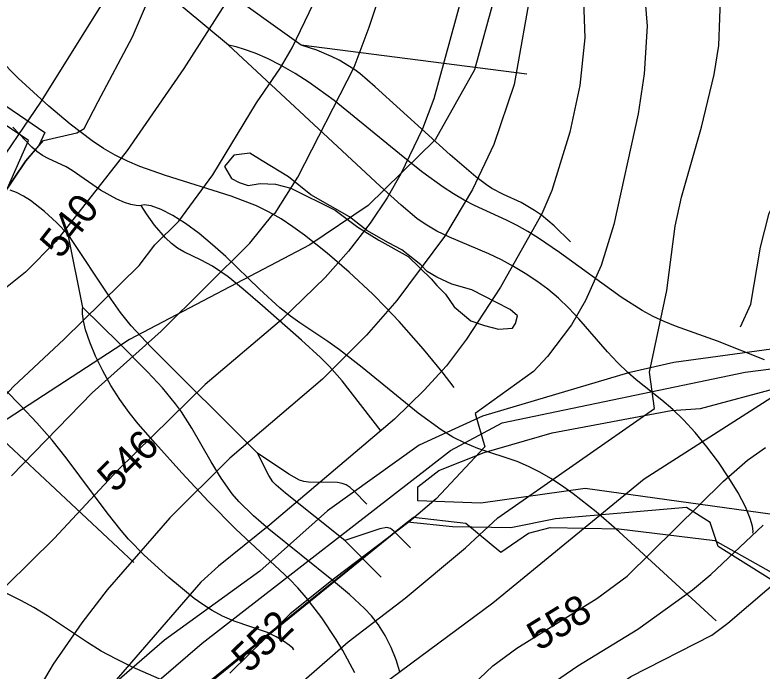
# Model space of a CAD drawing. Extents: x -709584 to -702006, y -1161789 to -1157496.
# Drawn here: x -708540.3 to -708283.8, y -1158766.7 to -1158541.7 of the extents above; entities that cross this region are included whole.
import ezdxf

# ---------------------------------------------------------------- set-up
doc = ezdxf.new("R2010")
doc.units = 0
for name, color, linetype in [('102_obvod PÚ', 7, 'Continuous'), ('110_silnice II. třídy a III. třídy', 7, 'Continuous'), ('120_vrstevnice hlavní', 7, 'Continuous'), ('121_vrstevnice hlavní_popis', 7, 'Continuous'), ('122_vrstevnice základní', 7, 'Continuous'), ('124_vrstevnice doplňková', 7, 'Continuous'), ('408_BPEJ_linie', 7, 'Continuous'), ('411_akumulovaný odtok', 7, 'Continuous'), ('419_LPIS PB', 7, 'Continuous')]:
    doc.layers.add(name, color=color, linetype=linetype)

msp = doc.modelspace()

# ---------------------------------------------------------------- linework, layer by layer
at = {"layer": '102_obvod PÚ'}
for points in [[(-708547.68, -1158611.72), (-708535.59, -1158584.74), (-708593.47, -1158546.09)], [(-707921.75, -1158971.03), (-707999.13, -1158885.41), (-708014.04, -1158899.97), (-708117.65, -1158840.95), (-708144.91, -1158823.83), (-708143.18, -1158817.96), (-708120.65, -1158790.72), (-708182.31, -1158754.97), (-708195.79, -1158778.16), (-708236.74, -1158752.81), (-708244.62, -1158757.84), (-708255.93, -1158750.88), (-708298.89, -1158724.01), (-708301.57, -1158715.74), (-708309.76, -1158710.63), (-708354.66, -1158714.54), (-708370.07, -1158717.61), (-708390.11, -1158717.27), (-708405.56, -1158715.63), (-708506.26, -1158796.6), (-708529.03, -1158816.51), (-708541.87, -1158842.13), (-708566.99, -1158883.81), (-708618.46, -1158935.49)]]:
    msp.add_lwpolyline(points, dxfattribs=at)
at = {"layer": '110_silnice II. třídy a III. třídy'}
msp.add_lwpolyline([(-708704.41, -1159007.15), (-708617.29, -1158919.6), (-708571.81, -1158874.15), (-708546.81, -1158830.34), (-708531.01, -1158804.51), (-708475.96, -1158757.15), (-708390.75, -1158691.13), (-708373.04, -1158681.56), (-708289.6, -1158664.21), (-708263.74, -1158660.86), (-708218.75, -1158674.74), (-708130.19, -1158710.62), (-708061.25, -1158767.55), (-707984.07, -1158831.3), (-707891.2, -1158926.02), (-707845.98, -1158974.16)], dxfattribs=at)
at = {"layer": '120_vrstevnice hlavní'}
for points in [[(-708409.92, -1158419.84), (-708416.34, -1158434.7), (-708434.49, -1158471.56), (-708444.2, -1158490.13), (-708455.2, -1158514.13), (-708468.35, -1158538.14), (-708482.35, -1158559.99), (-708501.78, -1158588.14), (-708526.21, -1158619.43), (-708536.64, -1158629.85), (-708559.07, -1158647.71)], [(-708345.48, -1158524.14), (-708344.63, -1158549.56), (-708346.34, -1158565.85), (-708349.77, -1158581.85), (-708355.91, -1158601.85), (-708359.34, -1158609.85), (-708373.63, -1158635), (-708385.2, -1158652.86), (-708392.06, -1158662), (-708399.77, -1158670.43), (-708409.92, -1158680.28), (-708452.78, -1158716.57), (-708470.35, -1158730.72), (-708476.49, -1158736.29), (-708506.21, -1158770.57), (-708513.62, -1158779.44), (-708518.35, -1158786.4), (-708533.12, -1158807.02), (-708523.37, -1158816.78), (-708575.5, -1158908.3)], [(-708494.35, -1158934.3), (-708464.92, -1158897.29), (-708460.06, -1158889.01), (-708440.2, -1158848.15), (-708435.92, -1158840.72), (-708430.77, -1158833.29), (-708424.77, -1158826.29), (-708414.49, -1158817.15), (-708400.34, -1158809.01), (-708394.34, -1158804.15), (-708378.06, -1158788.86), (-708366.06, -1158779.57), (-708356.91, -1158771.72), (-708347.06, -1158765), (-708326.48, -1158752.43), (-708307.62, -1158738.86), (-708301.34, -1158733.57), (-708283.34, -1158716.72)]]:
    msp.add_lwpolyline(points, dxfattribs=at)
at = {"layer": '122_vrstevnice základní'}
for points in [[(-708359.2, -1158388.56), (-708364.01, -1158398.84), (-708367.5, -1158412.36), (-708369.25, -1158425.89), (-708374.63, -1158482.13), (-708376.34, -1158492.13), (-708387.06, -1158536.14), (-708396.49, -1158570.42), (-708400.34, -1158580.71), (-708407.77, -1158596.14), (-708412.49, -1158604.42), (-708418.34, -1158613.14), (-708425.77, -1158622.71), (-708433.77, -1158631.71), (-708448.78, -1158646.28), (-708474.92, -1158668.43), (-708504.92, -1158697.86), (-708526.78, -1158721.29), (-708543.21, -1158737.43)], [(-708422.34, -1158397.27), (-708431.34, -1158415.56), (-708438.35, -1158426.99), (-708472.2, -1158475.99), (-708487.06, -1158501.56), (-708497.49, -1158517.13), (-708531.49, -1158571.57), (-708549.35, -1158597.71), (-708575.78, -1158629.28), (-708597.5, -1158656.28), (-708622.78, -1158686.14), (-708642.07, -1158713.86), (-708659.5, -1158736.57), (-708677.79, -1158762.15), (-708685.64, -1158775.86), (-708700.36, -1158805.58), (-708711.65, -1158830.72), (-708716.22, -1158842.15), (-708721.93, -1158860.44), (-708724.79, -1158871.87), (-708732.22, -1158910.73), (-708735.5, -1158924.44), (-708739.07, -1158933.58)], [(-708360.32, -1158513.61), (-708362.77, -1158531.28), (-708368.91, -1158565.56), (-708375.91, -1158586.14), (-708383.2, -1158601.57), (-708392.77, -1158617.71), (-708409.2, -1158639.57), (-708419.63, -1158651.57), (-708434.63, -1158666.57), (-708466.49, -1158693.71), (-708487.06, -1158714.14), (-708508.64, -1158738.86), (-708517.35, -1158750.15), (-708527.21, -1158764.43), (-708541.07, -1158788.01), (-708554.07, -1158812.72), (-708557.35, -1158820.72), (-708568.49, -1158843.47), (-708576.84, -1158861.02), (-708581.85, -1158872.45), (-708572.39, -1158881.09)], [(-708541.49, -1158699.72), (-708513.78, -1158671.28), (-708490.06, -1158650.14), (-708459.63, -1158620), (-708451.63, -1158610), (-708450.92, -1158609.71), (-708443.2, -1158597.28), (-708423.77, -1158559.56), (-708418.63, -1158545.85), (-708407.49, -1158512.13)], [(-708324.77, -1158525.56), (-708323.2, -1158545.56), (-708324.2, -1158561.85), (-708326.34, -1158575.57), (-708334.63, -1158613.57), (-708339.06, -1158627.57), (-708344.34, -1158639.57), (-708349.2, -1158648), (-708357.48, -1158658.86), (-708362.2, -1158664), (-708382.24, -1158678.4), (-708378.9, -1158689.81), (-708395.63, -1158707.72), (-708404.92, -1158715.57), (-708430.49, -1158734.86), (-708445.78, -1158747.15), (-708466.49, -1158767.43)], [(-708497.63, -1158627.57), (-708492.21, -1158620.57), (-708484.06, -1158612.43), (-708472.35, -1158596.57), (-708457.35, -1158571.85), (-708449.06, -1158559.85), (-708445.06, -1158552.99), (-708436.35, -1158534.71)], [(-708320.68, -1158676.72), (-708322.42, -1158664.17), (-708316.48, -1158636.14), (-708313.62, -1158614.14), (-708311.48, -1158604.14), (-708304.62, -1158580.14), (-708300.2, -1158562.14), (-708298.62, -1158552.14), (-708297.91, -1158533.28)], [(-708684.21, -1158935.3), (-708681.5, -1158923.01), (-708679.64, -1158911.01), (-708669.1, -1158869.34), (-708661.93, -1158849.58), (-708648.5, -1158819.86), (-708643.35, -1158810.15), (-708641.78, -1158808.15), (-708629.64, -1158783), (-708617.78, -1158762.43), (-708600.78, -1158735.72), (-708582.5, -1158713.14), (-708568.78, -1158697.86), (-708558.5, -1158688.14), (-708540.78, -1158669.14), (-708523.35, -1158652.86), (-708497.63, -1158627.57)], [(-708275, -1158669.48), (-708324.3, -1158700.96), (-708376.2, -1158743.43), (-708432.77, -1158785.29), (-708441.92, -1158793.29), (-708447.49, -1158799.15), (-708453.49, -1158806.86), (-708459.49, -1158816.58), (-708467.63, -1158832.15), (-708485.63, -1158869.87), (-708502.06, -1158896.01), (-708530.06, -1158932.87)], [(-708552.78, -1158935.01), (-708529.89, -1158907.3), (-708524.06, -1158899.3), (-708510.06, -1158877.29), (-708502.92, -1158863.29), (-708485.21, -1158824.72), (-708474.78, -1158807.58), (-708465.92, -1158795.58), (-708456.92, -1158785.29), (-708446.49, -1158774.72), (-708425.92, -1158756.72), (-708406.34, -1158741.72), (-708385.63, -1158724.43), (-708374.49, -1158714.14), (-708320.68, -1158676.72)], [(-708534.35, -1158961.58), (-708507.06, -1158925.87), (-708486.35, -1158900.29), (-708467.78, -1158871.01), (-708462.35, -1158860.72), (-708450.63, -1158835.01), (-708445.06, -1158826.44), (-708435.92, -1158815.01), (-708426.49, -1158806.01), (-708399.34, -1158786.86), (-708376.2, -1158765), (-708367.91, -1158758.86), (-708340.48, -1158741.86), (-708330.06, -1158734.15), (-708297.05, -1158701.57), (-708288.77, -1158694.43), (-708282.62, -1158690)], [(-708466.2, -1158933.58), (-708454.92, -1158919.01), (-708438.77, -1158895.01), (-708430.06, -1158879.29), (-708422.34, -1158862.72), (-708416.63, -1158852.29), (-708409.92, -1158842.01), (-708401.63, -1158831.86), (-708393.34, -1158823.86), (-708384.2, -1158816.43), (-708370.77, -1158807.01), (-708364.34, -1158801.58), (-708348.48, -1158784.72), (-708338.63, -1158775.57), (-708328.77, -1158768.57), (-708301.05, -1158754.43), (-708295.48, -1158750.29), (-708275.05, -1158732.86)]]:
    msp.add_lwpolyline(points, dxfattribs=at)
at = {"layer": '124_vrstevnice doplňková'}
msp.add_lwpolyline([(-708291.17, -1158648.71), (-708287.62, -1158640.86), (-708284.34, -1158621.28), (-708281.34, -1158609.71), (-708274.48, -1158597), (-708271.62, -1158594.71), (-708268.91, -1158593.28), (-708265.05, -1158592.28), (-708257, -1158592.5), (-708250.77, -1158593.71), (-708241.62, -1158596.57), (-708235.91, -1158599.14), (-708211.05, -1158608.14), (-708183.91, -1158612.43), (-708163.76, -1158619.14), (-708152.76, -1158625), (-708141.33, -1158633.43), (-708128.05, -1158645.43)], dxfattribs=at)
at = {"layer": '408_BPEJ_linie'}
for points in [[(-708179.5, -1158340), (-708195, -1158326), (-708220.5, -1158309.5), (-708230, -1158305), (-708248.5, -1158300.5), (-708267, -1158302), (-708293.5, -1158316), (-708331, -1158346), (-708357, -1158377.5), (-708373, -1158418), (-708377, -1158472), (-708375.5, -1158535), (-708382.5, -1158560.5), (-708396, -1158584.5), (-708419, -1158607), (-708439, -1158620.5), (-708501, -1158653), (-708548, -1158683.5)], [(-708587.68, -1158542.71), (-708530, -1158582), (-708532.06, -1158586.46), (-708536.54, -1158591.7), (-708545.05, -1158604.26)], [(-708561, -1158876.5), (-708526, -1158813.5), (-708403.5, -1158714), (-708385.5, -1158716), (-708373.5, -1158726), (-708364, -1158719.5), (-708356.5, -1158717.5), (-708333, -1158718), (-708300, -1158722), (-708242, -1158754.5), (-708234.5, -1158752.5), (-708224, -1158757), (-708218, -1158760), (-708196.5, -1158772.5), (-708192.5, -1158772.5), (-708179.5, -1158753), (-708118, -1158789.5), (-708142, -1158821.5), (-708113.5, -1158841), (-708097, -1158849), (-708011.5, -1158897.5), (-707999.5, -1158885.5), (-707996, -1158885.5), (-707920, -1158970)]]:
    msp.add_lwpolyline(points, dxfattribs=at)
at = {"layer": '411_akumulovaný odtok'}
for p, q in [((-708364.49, -1158562), (-708441.99, -1158552)), ((-708516.99, -1158642), (-708521.99, -1158617)), ((-708414.49, -1158734.5), (-708426.99, -1158722))]:
    msp.add_line(p, q, dxfattribs=at)
for points in [[(-708466.99, -1158552), (-708489.92, -1158532.81), (-708494.44, -1158529.36), (-708497.33, -1158527.8), (-708499.35, -1158527.26), (-708504.32, -1158526.45), (-708505.15, -1158526.12), (-708505.86, -1158525.53), (-708506.38, -1158524.64), (-708506.94, -1158522.3), (-708507.08, -1158519.79), (-708506.99, -1158517)], [(-708441.99, -1158552), (-708469.72, -1158532.12), (-708473.38, -1158529.62), (-708477.18, -1158527.38), (-708481.09, -1158525.66), (-708485.13, -1158524.2), (-708506.99, -1158517)], [(-708282.95, -1158660), (-708299.03, -1158653.58), (-708313.46, -1158648.41), (-708317.37, -1158646.85), (-708321.13, -1158645.13), (-708324.89, -1158643.1), (-708332.15, -1158638.48), (-708353.32, -1158623.14), (-708360.48, -1158618.26), (-708364.15, -1158615.98), (-708367.89, -1158613.87), (-708371.5, -1158612.07), (-708382.47, -1158606.99), (-708386.05, -1158605.16), (-708389.71, -1158603.02), (-708393.28, -1158600.7), (-708400.22, -1158595.69), (-708407.01, -1158590.38), (-708430.63, -1158571), (-708439.28, -1158564.81), (-708444.05, -1158561.78), (-708448.88, -1158559), (-708453.58, -1158556.62), (-708457.76, -1158554.83), (-708461.41, -1158553.49), (-708464.32, -1158552.58), (-708466.99, -1158552)], [(-708286.99, -1158719.5), (-708286.82, -1158718.8), (-708287.07, -1158717.05), (-708287.81, -1158714.45), (-708289.5, -1158710.39), (-708291.99, -1158705.64), (-708295.14, -1158700.47), (-708298.78, -1158695.13), (-708302.71, -1158689.88), (-708306.75, -1158684.96), (-708310.69, -1158680.62), (-708314.4, -1158677.05), (-708318.13, -1158673.81), (-708327.04, -1158666.8), (-708329.91, -1158664.35), (-708333.45, -1158660.92), (-708336.82, -1158657.27), (-708346.67, -1158645.9), (-708350.09, -1158642.24), (-708353.68, -1158638.78), (-708357.3, -1158635.76), (-708361.11, -1158632.97), (-708365.06, -1158630.37), (-708369.12, -1158627.95), (-708373.28, -1158625.7), (-708377.53, -1158623.64), (-708391.05, -1158617.92), (-708395.39, -1158615.86), (-708399.49, -1158613.48), (-708402.3, -1158611.48), (-708407.64, -1158606.97), (-708414.91, -1158600.39), (-708466.99, -1158552)], [(-708349.49, -1158619.5), (-708355.2, -1158613.96), (-708359.53, -1158610.38), (-708361.86, -1158608.72), (-708366.51, -1158606.06), (-708372.6, -1158603.26), (-708376.51, -1158601.19), (-708378.42, -1158599.95), (-708382.08, -1158597.21), (-708390.82, -1158589.66), (-708416.63, -1158566.3), (-708421.9, -1158561.78), (-708423.96, -1158560.24), (-708428.94, -1158557.17), (-708431.57, -1158555.87), (-708436.63, -1158553.78), (-708441.99, -1158552)], [(-708389.49, -1158669.5), (-708393.63, -1158664.1), (-708399.98, -1158656.27), (-708408.31, -1158646.85), (-708412.91, -1158642.04), (-708417.45, -1158637.5), (-708425.53, -1158629.95), (-708433.09, -1158623.41), (-708440.84, -1158617.21), (-708444.83, -1158614.32), (-708448.93, -1158611.62), (-708453.18, -1158609.2), (-708457.36, -1158607.2), (-708466.07, -1158603.84), (-708488.55, -1158596.74), (-708497.39, -1158593.63), (-708501.69, -1158591.84), (-708505.85, -1158589.81), (-708509.91, -1158587.46), (-708513.82, -1158584.86), (-708521.36, -1158579.14), (-708528.63, -1158572.99), (-708539.17, -1158563.34), (-708545.86, -1158556.68)], [(-708496.99, -1158607), (-708497.48, -1158607.11), (-708498.7, -1158607.02), (-708500.49, -1158606.68), (-708502.7, -1158606.01), (-708505.32, -1158604.91), (-708510.9, -1158601.72), (-708520.6, -1158595.04), (-708522.72, -1158593.81), (-708528.91, -1158590.93), (-708530.87, -1158589.83), (-708532.71, -1158588.5), (-708534.46, -1158586.99), (-708541.04, -1158580.17)], [(-708521.99, -1158617), (-708526, -1158612.88), (-708530.12, -1158609.07), (-708534.9, -1158605.32), (-708537.35, -1158603.78), (-708539.71, -1158602.6), (-708541.91, -1158601.78)], [(-708299.49, -1158749.5), (-708332.78, -1158718.97), (-708340.75, -1158712.09), (-708348.58, -1158705.91), (-708352.61, -1158703.05), (-708356.3, -1158700.69), (-708360.08, -1158698.53), (-708363.94, -1158696.57), (-708367.88, -1158694.87), (-708381.31, -1158690.36), (-708385.67, -1158688.62), (-708389.89, -1158686.47), (-708393.97, -1158683.97), (-708401.86, -1158678.3), (-708421.08, -1158662.63), (-708428.89, -1158656.53), (-708432.89, -1158653.66), (-708442.52, -1158647.26), (-708445.65, -1158645.04), (-708449.33, -1158642.12), (-708456.31, -1158635.74), (-708467.85, -1158624.56), (-708472.4, -1158620.51), (-708477.06, -1158616.66), (-708481.67, -1158613.23), (-708486.07, -1158610.42), (-708490.06, -1158608.39), (-708493.51, -1158607.2), (-708495.94, -1158606.78), (-708496.99, -1158607)], [(-708414.49, -1158684.5), (-708427.91, -1158667.24), (-708432.28, -1158662.27), (-708435.41, -1158659.16), (-708441.94, -1158653.2), (-708455.27, -1158641.5), (-708461.97, -1158635.72), (-708467.09, -1158631.54), (-708472.46, -1158627.81), (-708476.37, -1158625.74), (-708482.34, -1158622.89), (-708484.42, -1158621.65), (-708486.56, -1158620.04), (-708488.62, -1158618.12), (-708492.32, -1158613.82), (-708495.16, -1158609.87), (-708496.99, -1158607)], [(-708456.99, -1158692), (-708493.59, -1158655.48), (-708500.42, -1158648.28), (-708504.02, -1158643.79), (-708507.3, -1158639.15), (-708521.99, -1158617)], [(-708499.49, -1158729.5), (-708564.12, -1158669.13), (-708569.58, -1158663.89), (-708573.08, -1158660.3), (-708576.49, -1158656.17), (-708579.9, -1158650.84), (-708582.98, -1158645.2), (-708586.99, -1158637)], [(-708423.55, -1158767.35), (-708427.67, -1158759.65), (-708429.95, -1158755.89), (-708434.87, -1158748.53), (-708440.25, -1158741.5), (-708443.17, -1158738.16), (-708446.01, -1158735.21), (-708464.44, -1158718.13), (-708473.84, -1158708.55), (-708483.01, -1158698.7), (-708492.03, -1158688.71), (-708497.93, -1158681.94), (-708501.03, -1158678.02), (-708504.22, -1158673.57), (-708507.31, -1158668.76), (-708510.16, -1158663.74), (-708512.63, -1158658.73), (-708514.61, -1158653.97), (-708516.01, -1158649.67), (-708516.71, -1158646.61), (-708517.06, -1158644.21), (-708517.14, -1158642.62), (-708516.99, -1158642)], [(-708408.18, -1158767.05), (-708409.43, -1158762.86), (-708411.13, -1158758.64), (-708413.17, -1158754.59), (-708415.45, -1158750.92), (-708417.84, -1158747.79), (-708420.27, -1158745.25), (-708425.46, -1158740.5), (-708430.9, -1158735.95), (-708453.1, -1158718.13), (-708458.42, -1158713.5), (-708463.41, -1158708.59), (-708465.69, -1158705.97), (-708469.51, -1158700.63), (-708472.93, -1158694.97), (-708479.52, -1158683.41), (-708483.09, -1158677.82), (-708485.17, -1158675.02), (-708489.66, -1158669.64), (-708494.79, -1158664.1), (-708504.5, -1158654.29), (-708516.99, -1158642)], [(-708444.49, -1158759.5), (-708444.87, -1158758.89), (-708446.09, -1158757.85), (-708448.03, -1158756.5), (-708450.57, -1158755.02), (-708453.61, -1158753.57), (-708465.06, -1158749.67), (-708468.99, -1158747.95), (-708472.62, -1158745.99), (-708475.79, -1158743.95), (-708478.75, -1158741.81), (-708487.5, -1158734.69), (-708495.95, -1158726.97), (-708501.27, -1158721.48), (-708503.82, -1158718.54), (-708508.67, -1158712.43), (-708522.68, -1158693.6), (-708527.55, -1158687.5), (-708532.72, -1158681.61), (-708538.1, -1158675.89), (-708554.68, -1158659.14)], [(-708419.49, -1158709.5), (-708423.76, -1158705.08), (-708425.24, -1158703.78), (-708426.54, -1158702.91), (-708427.97, -1158702.37), (-708429.53, -1158702.12), (-708439.46, -1158701.92), (-708441.06, -1158701.71), (-708442.62, -1158701.26), (-708446.3, -1158699.24), (-708456.99, -1158692)], [(-708426.99, -1158722), (-708447.41, -1158705.72), (-708450.59, -1158702.99), (-708451.72, -1158701.79), (-708453.15, -1158699.7), (-708456.99, -1158692)], [(-708404.49, -1158724.5), (-708410.18, -1158718.71), (-708411.3, -1158717.85), (-708412.55, -1158717.46), (-708414.97, -1158717.93), (-708426.99, -1158722)], [(-708459.49, -1158784.5), (-708460.08, -1158783.78), (-708462.16, -1158782.43), (-708465.53, -1158780.63), (-708475.28, -1158776.14), (-708499.9, -1158765.38), (-708505.63, -1158762.61), (-708510.67, -1158759.89), (-708515.37, -1158756.98), (-708529.09, -1158747.81), (-708533.79, -1158744.96), (-708538.21, -1158742.59), (-708551.73, -1158735.83)]]:
    msp.add_lwpolyline(points, dxfattribs=at)
at = {"layer": '419_LPIS PB'}
for points in [[(-708545.05, -1158604.26), (-708536.54, -1158591.7), (-708530.53, -1158584.68), (-708519.02, -1158582.16), (-708516.52, -1158580.66), (-708511.71, -1158571.32), (-708499.9, -1158549.2), (-708485.8, -1158516.2)], [(-708278.06, -1158655.93), (-708314.1, -1158660.95), (-708329.62, -1158664.47), (-708379.75, -1158679.33), (-708401.55, -1158689.21), (-708432.98, -1158711.82), (-708456.16, -1158732.48), (-708488.99, -1158756.15), (-708526.06, -1158788.3), (-708540.57, -1158804.6)], [(-708272.8, -1158714.09), (-708344.5, -1158704.1), (-708380.3, -1158709.2), (-708402, -1158708.3), (-708402, -1158703.5), (-708394.8, -1158698), (-708379.23, -1158691.81), (-708355.88, -1158685.05), (-708314.94, -1158677.35), (-708304.95, -1158676.71), (-708277.51, -1158669.39)]]:
    msp.add_lwpolyline(points, dxfattribs=at)
msp.add_lwpolyline([(-708465.98, -1158597.74), (-708463.34, -1158599.15), (-708460.16, -1158600.21), (-708456.11, -1158599.5), (-708450.81, -1158599.68), (-708445.52, -1158601.09), (-708430.35, -1158608.68), (-708422.59, -1158614.5), (-708415.36, -1158618.91), (-708405.31, -1158624.55), (-708397.37, -1158632.14), (-708395.43, -1158634.43), (-708392.43, -1158637.43), (-708389.43, -1158641.84), (-708383.79, -1158646.6), (-708379.02, -1158648.19), (-708374.26, -1158649.42), (-708369.5, -1158649.07), (-708368.44, -1158647.48), (-708367.74, -1158644.84), (-708370.2, -1158642.72), (-708375.14, -1158640.25), (-708383.43, -1158636.02), (-708390.31, -1158634.08), (-708395.43, -1158631.61), (-708398.78, -1158629.67), (-708400.9, -1158627.37), (-708407.42, -1158622.26), (-708412.01, -1158619.79), (-708419.42, -1158615.56), (-708425.41, -1158610.97), (-708438.64, -1158603.39), (-708446.4, -1158597.21), (-708455.4, -1158591.74), (-708459.63, -1158589.1), (-708465.1, -1158589.8), (-708468.28, -1158593.68)], close=True, dxfattribs=at)

# ---------------------------------------------------------------- texts
at = {"layer": '121_vrstevnice hlavní_popis'}
for s, rotation, p in [('540', 51.77, (-708524.68, -1158625.71)), ('546', 44.7703, (-708506, -1158705.93)), ('558', 31.5595, (-708360.43, -1158760.06)), ('552', 44.2852, (-708459.95, -1158767.78))]:
    msp.add_text(s, height=10, rotation=rotation, dxfattribs=at).set_placement(p)

doc.saveas('drawing.dxf')
